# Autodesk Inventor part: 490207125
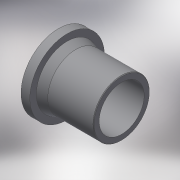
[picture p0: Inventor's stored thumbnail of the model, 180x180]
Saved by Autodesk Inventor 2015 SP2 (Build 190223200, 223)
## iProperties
Created: 2017-07
Part Number: 490207125
Material: Generic
Description: Stub Flange 125
Document SubType Name: Modeling
Designer: Кирилл
Mass: 1001.01 g
Surface Area: 1563.03 cm^2
Volume: 1001.01 cm^3
Density: 1 g/cm^3
Appearance: Default
Author: Кирилл
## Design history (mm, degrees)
derived "490207.ipt"
feature "Solid1::490207.ipt"
tag "TaggingFeature1"
body "Solid1"
other parameters: "d0" = 182, "d1" = 132, "d2" = 125, "d4" = 158, "d5" = 25, "d6" = 132, "d16" = 125, "d17" = 2.5, "d18" = 2.5, "d19" = 2.5, "d21" = 2.5, "d24" = 2.5, "d25" = 2.5, "d26" = 1.25, "d27" = 0, "d32" = 1.25, "d_" = 125, "L_" = 182, "L_1" = 132, "D_" = 158, "D_1" = 132, "a_" = 25
